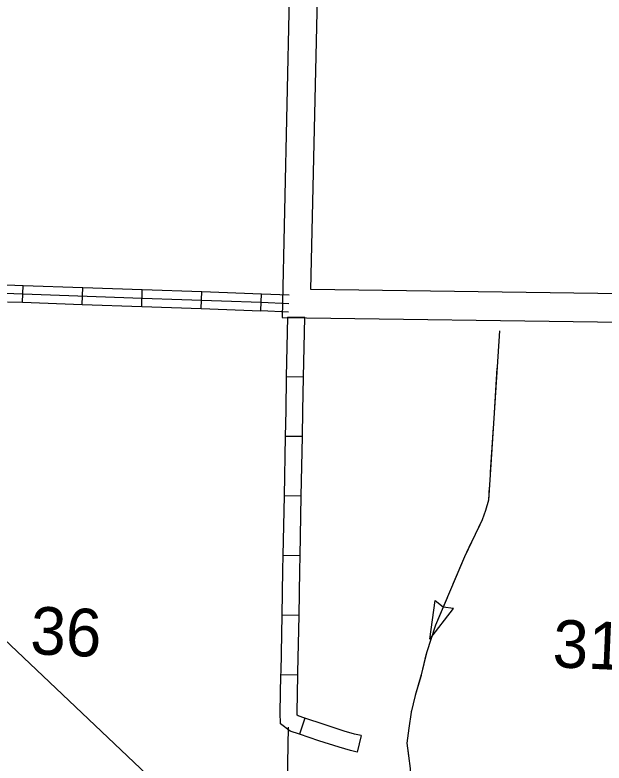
# Model space of a CAD drawing. Extents: x 1196286 to 1268366, y 2040822 to 2082115.
# Drawn here: x 1237691 to 1239648, y 2053727 to 2056211 of the extents above; entities that cross this region are included whole.
import ezdxf

# ---------------------------------------------------------------- set-up
doc = ezdxf.new("R2010")
doc.units = 0
for name, color, linetype in [('60', 7, 'Continuous'), ('61', 7, 'Continuous'), ('63', 7, 'Continuous'), ('Level 8', 7, 'Continuous'), ('Level 86', 7, 'Continuous'), ('Level 87', 7, 'Continuous')]:
    doc.layers.add(name, color=color, linetype=linetype)

msp = doc.modelspace()

# ---------------------------------------------------------------- linework, layer by layer
at = {"layer": '61'}
for p, q in [((1237716.3, 2055257.3), (1237718.2, 2055313.5)), ((1237914.1, 2055250.3), (1237916.1, 2055306.5)), ((1238112, 2055243.4), (1238114, 2055299.6)), ((1238309.9, 2055236.4), (1238311.9, 2055292.6)), ((1238507.6, 2055229.5), (1238509.9, 2055285.7)), ((1238653.5, 2055207), (1238597.3, 2055208.1)), ((1238649.8, 2055009), (1238593.5, 2055010.1)), ((1238646, 2054811.1), (1238589.8, 2054812.1)), ((1238642.2, 2054613.1), (1238586, 2054614.2)), ((1238638.5, 2054415.1), (1238582.2, 2054416.2)), ((1238634.7, 2054217.2), (1238578.5, 2054218.2)), ((1238631, 2054019.2), (1238574.7, 2054020.3)), ((1238654.3, 2053876.3), (1238636.3, 2053823.1)), ((1238840.9, 2053818.2), (1238827.6, 2053763.5))]:
    msp.add_line(p, q, dxfattribs=at)
for points in [[(1237520.4, 2055320.4), (1237718.2, 2055313.5)], [(1237321.5, 2055299.3), (1237717.2, 2055285.4), (1238113, 2055271.5), (1238508.8, 2055257.6), (1238600.4, 2055253.7)], [(1237718.2, 2055313.5), (1237916.1, 2055306.5)], [(1237916.1, 2055306.5), (1238114, 2055299.6)], [(1238114, 2055299.6), (1238311.9, 2055292.6)], [(1238311.9, 2055292.6), (1238509.7, 2055285.7)], [(1238509.9, 2055285.7), (1238601.6, 2055281.8)], [(1237665.7, 2055259), (1237716.3, 2055257.3)], [(1237716.3, 2055257.3), (1237914.1, 2055250.3)], [(1237914.1, 2055250.3), (1238112, 2055243.4)], [(1238112, 2055243.4), (1238309.9, 2055236.4)], [(1238309.9, 2055236.4), (1238507.8, 2055229.4)], [(1238507.6, 2055229.5), (1238599.2, 2055225.6)], [(1238593.5, 2055010.1), (1238597.3, 2055208.1)], [(1238649.8, 2055009), (1238653.5, 2055207)], [(1238589.8, 2054812.1), (1238591.4, 2054897.9), (1238593.5, 2055010.1)], [(1238646, 2054811.1), (1238647.6, 2054896.9), (1238649.8, 2055009)], [(1238586, 2054614.2), (1238589.8, 2054812.1)], [(1238642.2, 2054613.1), (1238646, 2054811.1)], [(1238582.2, 2054416.2), (1238586, 2054614.2)], [(1238638.5, 2054415.1), (1238642.2, 2054613.1)], [(1238578.5, 2054218.2), (1238581.3, 2054368), (1238582.2, 2054416.2)], [(1238634.7, 2054217.2), (1238637.6, 2054367), (1238638.5, 2054415.1)], [(1238574.7, 2054020.3), (1238574.9, 2054028.9), (1238578.5, 2054218.2)], [(1238631, 2054019.2), (1238631.1, 2054027.8), (1238634.7, 2054217.2)], [(1238636.3, 2053823.1), (1238605.5, 2053833.5), (1238573.6, 2053857), (1238572.3, 2053895.4), (1238574.7, 2054020.3)], [(1238654.3, 2053876.3), (1238631.8, 2053884), (1238628.9, 2053886.1), (1238628.6, 2053895.8), (1238631, 2054019.2)], [(1238840.9, 2053818.2), (1238819.4, 2053823.4), (1238784.2, 2053833.2), (1238718.3, 2053854.7), (1238654.3, 2053876.3)], [(1238827.6, 2053763.5), (1238805.1, 2053769), (1238768, 2053779.4), (1238700.6, 2053801.3), (1238636.3, 2053823.1)]]:
    msp.add_lwpolyline(points, dxfattribs=at)
at = {"layer": '63'}
for p, q in [((1239068.8, 2054139), (1239086.4, 2054266.4)), ((1239086.4, 2054266.4), (1239113.4, 2054245.4)), ((1239068.8, 2054139), (1239147.8, 2054240.5)), ((1239147.8, 2054240.5), (1239113.9, 2054245.2))]:
    msp.add_line(p, q, dxfattribs=at)
for points in [[(1239300.2, 2055162), (1239268, 2054667.3), (1239263.6, 2054600), (1239254.3, 2054566), (1239242.9, 2054535), (1239183.8, 2054411.7), (1239088.3, 2054185.2), (1239057.6, 2054092.6), (1239040.4, 2054019.9), (1239020.7, 2053951.1), (1239006.9, 2053896.1), (1238999.1, 2053842.8), (1238992.9, 2053793.7), (1239003.5, 2053708.5), (1239009.8, 2053629), (1239015.5, 2053573.6), (1239013.3, 2053501.4), (1239009.1, 2053385.2), (1239008.3, 2053284.4), (1239005.1, 2053236), (1238794.7, 2053250.3), (1238627.2, 2053250.7), (1238589.8, 2053253.3), (1238544, 2053267.4)], [(1239300.2, 2055162), (1239268, 2054667.3), (1239263.6, 2054600), (1239254.3, 2054566), (1239242.9, 2054535), (1239183.8, 2054411.7), (1239088.3, 2054185.2), (1239057.6, 2054092.6), (1239040.4, 2054019.9), (1239020.7, 2053951.1), (1239006.9, 2053896.1), (1238999.1, 2053842.8), (1238992.9, 2053793.7), (1239003.5, 2053708.5), (1239009.8, 2053629), (1239015.5, 2053573.6), (1239013.3, 2053501.4), (1239009.1, 2053385.2), (1239008.3, 2053284.4), (1239005.1, 2053236), (1238794.7, 2053250.3), (1238627.2, 2053250.7), (1238589.8, 2053253.3), (1238544, 2053267.4)], [(1239292.2, 2055038.5), (1239282.5, 2054890.4)], [(1239279.3, 2054841), (1239269.6, 2054692.8)], [(1239266.4, 2054643.4), (1239263.6, 2054600), (1239254.3, 2054566), (1239242.9, 2054535), (1239227, 2054501.9)], [(1239205.6, 2054457.2), (1239183.8, 2054411.7), (1239145.7, 2054321.4)], [(1239126.5, 2054275.8), (1239088.3, 2054185.2), (1239082.8, 2054168.6)], [(1239057.1, 2054090.5), (1239040.4, 2054019.9), (1239039.9, 2054018.3)], [(1239039.9, 2054018.3), (1239020.7, 2053951.1), (1239019.6, 2053946.9)], [(1239007.6, 2053898.9), (1239006.9, 2053896.1), (1238999.1, 2053842.8), (1238992.9, 2053793.7), (1238998.1, 2053751.7)]]:
    msp.add_lwpolyline(points, dxfattribs=at)
at = {"layer": 'Level 8'}
msp.add_line((1243668.8, 2048450.6), (1232402.8, 2059105.7), dxfattribs=at)
at = {"layer": 'Level 86'}
msp.add_lwpolyline([(1238553.7, 2050935.3), (1238553.1, 2051090.4), (1238588.2, 2053246.6), (1238599.5, 2053846.2)], dxfattribs=at)
at = {"layer": 'Level 87'}
for p, q in [((1238622.8, 2057203), (1238578.4, 2055207.2)), ((1238674.2, 2055299.6), (1238716.5, 2057200.7)), ((1240789.6, 2055269.3), (1238674.2, 2055299.6)), ((1238578.4, 2055207.2), (1240694.1, 2055176.9))]:
    msp.add_line(p, q, dxfattribs=at)

# ---------------------------------------------------------------- texts
at = {"layer": '60'}
for s, p in [('36', (1237739.7, 2054089.1)), ('31', (1239474.8, 2054045.6))]:
    msp.add_text(s, height=158.4, rotation=357.548, dxfattribs=at).set_placement(p)

doc.saveas('drawing.dxf')
